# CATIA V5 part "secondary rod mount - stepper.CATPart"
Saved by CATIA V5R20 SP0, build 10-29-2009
Part number: secondary rod mount - stepper
Source: Unknown
Bounding box of the stored display mesh (mm): x 0 to 57.3, y -10 to 78.3, z -46 to 0
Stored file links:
  C:\Users\Ikarus\OneDrive - FH JOANNEUM\BAC - Arbeit 1\CAD Modell\CAD-Modell-Step files\rod mount\secondary\secondary rod mount - stepper.CATPart
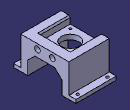
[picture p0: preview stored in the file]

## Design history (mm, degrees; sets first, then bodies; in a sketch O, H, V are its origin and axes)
Body1 (main body)
  Solid1 "Hauptkörper": solid without history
